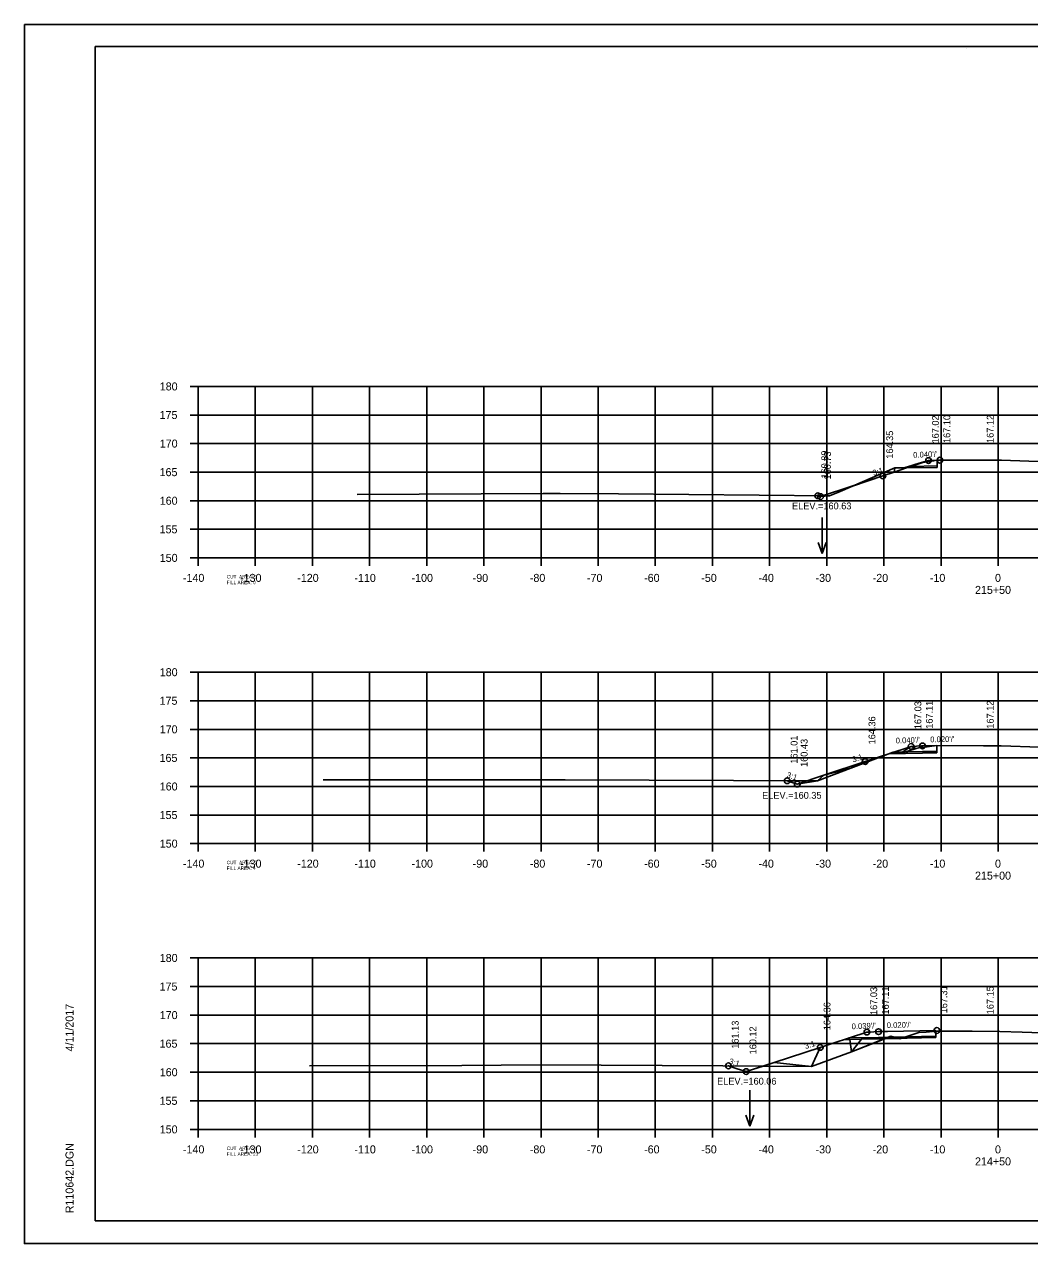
# Model space of a CAD drawing. Extents: x 1368503 to 1373085, y 379840 to 381833.
# Drawn here: x 1368502.7 to 1368678.6, y 381406.1 to 381619.4 of the extents above; entities that cross this region are included whole.
import ezdxf

# ---------------------------------------------------------------- set-up
doc = ezdxf.new("R2010")
doc.units = 0
for name, color, linetype in [('S_BRIDGE', 7, 'Continuous'), ('S_EDGE_PAVEMENT', 7, 'Continuous'), ('S_GRAVEL_ROAD', 7, 'Continuous'), ('S_MISC_BOUNDARY', 7, 'Continuous'), ('S_OBSCURES', 7, 'Continuous'), ('S_PHOTO_CENTERS', 7, 'Continuous'), ('S_PHOTO_NOTES', 7, 'Continuous'), ('S_RDW_PT_SYM', 7, 'Continuous'), ('S_SHOULDER', 7, 'Continuous'), ('S_STREAM_ANNOT', 7, 'Continuous'), ('S_TRAILS', 7, 'Continuous'), ('S_TRAILS_ANNOT', 7, 'Continuous'), ('S_TREE', 7, 'Continuous')]:
    doc.layers.add(name, color=color, linetype=linetype)

msp = doc.modelspace()

# ---------------------------------------------------------------- linework, layer by layer
at = {"layer": 'S_BRIDGE'}
for p, q in [((1368515.06, 381615.52), (1368831.24, 381615.52)), ((1368515.06, 381410.06), (1368515.06, 381615.52)), ((1368667.58, 381615.26), (1368667.58, 381615.26)), ((1368667.58, 381615.26), (1368667.58, 381615.26)), ((1368515.06, 381410.06), (1368515.06, 381410.06)), ((1368831.24, 381410.06), (1368515.06, 381410.06))]:
    msp.add_line(p, q, dxfattribs=at)
at = {"layer": 'S_EDGE_PAVEMENT'}
for p, q in [((1368531.66, 381556.06), (1368533.06, 381556.06)), ((1368533.06, 381526.06), (1368533.06, 381556.06)), ((1368531.66, 381551.06), (1368533.06, 381551.06)), ((1368531.66, 381546.06), (1368533.06, 381546.06)), ((1368531.66, 381541.06), (1368533.06, 381541.06)), ((1368531.66, 381536.06), (1368533.06, 381536.06)), ((1368531.66, 381531.06), (1368533.06, 381531.06)), ((1368531.66, 381526.06), (1368533.06, 381526.06)), ((1368533.06, 381526.06), (1368813.06, 381526.06)), ((1368533.06, 381524.66), (1368533.06, 381526.06)), ((1368543.06, 381524.66), (1368543.06, 381526.06)), ((1368553.06, 381524.66), (1368553.06, 381526.06)), ((1368563.06, 381524.66), (1368563.06, 381526.06)), ((1368573.06, 381524.66), (1368573.06, 381526.06)), ((1368583.06, 381524.66), (1368583.06, 381526.06)), ((1368593.06, 381524.66), (1368593.06, 381526.06)), ((1368603.06, 381524.66), (1368603.06, 381526.06)), ((1368613.06, 381524.66), (1368613.06, 381526.06)), ((1368623.06, 381524.66), (1368623.06, 381526.06)), ((1368633.06, 381524.66), (1368633.06, 381526.06)), ((1368643.06, 381524.66), (1368643.06, 381526.06)), ((1368653.06, 381524.66), (1368653.06, 381526.06)), ((1368663.06, 381524.66), (1368663.06, 381526.06)), ((1368673.06, 381524.66), (1368673.06, 381526.06)), ((1368531.66, 381506.06), (1368533.06, 381506.06)), ((1368533.06, 381476.06), (1368533.06, 381506.06)), ((1368531.66, 381501.06), (1368533.06, 381501.06)), ((1368531.66, 381496.06), (1368533.06, 381496.06)), ((1368531.66, 381491.06), (1368533.06, 381491.06)), ((1368531.66, 381486.06), (1368533.06, 381486.06)), ((1368531.66, 381481.06), (1368533.06, 381481.06)), ((1368531.66, 381476.06), (1368533.06, 381476.06)), ((1368533.06, 381476.06), (1368813.06, 381476.06)), ((1368533.06, 381474.66), (1368533.06, 381476.06)), ((1368543.06, 381474.66), (1368543.06, 381476.06)), ((1368553.06, 381474.66), (1368553.06, 381476.06)), ((1368563.06, 381474.66), (1368563.06, 381476.06)), ((1368573.06, 381474.66), (1368573.06, 381476.06)), ((1368583.06, 381474.66), (1368583.06, 381476.06)), ((1368593.06, 381474.66), (1368593.06, 381476.06)), ((1368603.06, 381474.66), (1368603.06, 381476.06)), ((1368613.06, 381474.66), (1368613.06, 381476.06)), ((1368623.06, 381474.66), (1368623.06, 381476.06)), ((1368633.06, 381474.66), (1368633.06, 381476.06)), ((1368643.06, 381474.66), (1368643.06, 381476.06)), ((1368653.06, 381474.66), (1368653.06, 381476.06)), ((1368663.06, 381474.66), (1368663.06, 381476.06)), ((1368673.06, 381474.66), (1368673.06, 381476.06)), ((1368531.66, 381456.06), (1368533.06, 381456.06)), ((1368533.06, 381426.06), (1368533.06, 381456.06)), ((1368531.66, 381451.06), (1368533.06, 381451.06)), ((1368531.66, 381446.06), (1368533.06, 381446.06)), ((1368531.66, 381441.06), (1368533.06, 381441.06)), ((1368531.66, 381436.06), (1368533.06, 381436.06)), ((1368531.66, 381431.06), (1368533.06, 381431.06)), ((1368531.66, 381426.06), (1368533.06, 381426.06)), ((1368533.06, 381426.06), (1368813.06, 381426.06)), ((1368533.06, 381424.66), (1368533.06, 381426.06)), ((1368543.06, 381424.66), (1368543.06, 381426.06)), ((1368553.06, 381424.66), (1368553.06, 381426.06)), ((1368563.06, 381424.66), (1368563.06, 381426.06)), ((1368573.06, 381424.66), (1368573.06, 381426.06)), ((1368583.06, 381424.66), (1368583.06, 381426.06)), ((1368593.06, 381424.66), (1368593.06, 381426.06)), ((1368603.06, 381424.66), (1368603.06, 381426.06)), ((1368613.06, 381424.66), (1368613.06, 381426.06)), ((1368623.06, 381424.66), (1368623.06, 381426.06)), ((1368633.06, 381424.66), (1368633.06, 381426.06)), ((1368643.06, 381424.66), (1368643.06, 381426.06)), ((1368653.06, 381424.66), (1368653.06, 381426.06)), ((1368663.06, 381424.66), (1368663.06, 381426.06)), ((1368673.06, 381424.66), (1368673.06, 381426.06))]:
    msp.add_line(p, q, dxfattribs=at)
at = {"layer": 'S_GRAVEL_ROAD'}
for p, q in [((1368642.24, 381533.11), (1368642.24, 381526.82)), ((1368642.24, 381526.82), (1368641.54, 381528.75)), ((1368642.24, 381526.82), (1368642.94, 381528.75)), ((1368629.61, 381432.9), (1368629.61, 381426.61)), ((1368629.61, 381426.61), (1368628.91, 381428.54)), ((1368629.61, 381426.61), (1368630.31, 381428.54))]:
    msp.add_line(p, q, dxfattribs=at)
at = {"layer": 'S_MISC_BOUNDARY'}
for points in [[(1368560.89, 381537.13), (1368593.43, 381537.32), (1368594.68, 381537.33), (1368595.6, 381537.34), (1368596.42, 381537.33), (1368606.61, 381537.24), (1368643.53, 381536.94), (1368645.38, 381537.7), (1368654.95, 381541.84), (1368656.19, 381541.81), (1368656.53, 381541.81), (1368657.16, 381542.01), (1368659.22, 381542.66), (1368661.73, 381543.04), (1368662.39, 381543.13), (1368672.21, 381543.17), (1368673.63, 381543.17), (1368681.6, 381542.84)], [(1368554.91, 381487.22), (1368579.94, 381487.25), (1368591.4, 381487.25), (1368597.27, 381487.23), (1368641.43, 381487.04), (1368647.27, 381489.25), (1368654.66, 381492.05), (1368655.24, 381491.98), (1368655.98, 381491.86), (1368658.7, 381492.68), (1368659.18, 381492.84), (1368659.74, 381492.9), (1368662.32, 381493.22), (1368670.48, 381493.19), (1368673.59, 381493.17), (1368680.27, 381492.92)], [(1368552.55, 381437.16), (1368579.2, 381437.26), (1368592.98, 381437.37), (1368624.85, 381437.21), (1368640.41, 381437.08), (1368647.36, 381439.64), (1368654.29, 381442.35), (1368654.66, 381442.27), (1368655.85, 381441.92), (1368657.8, 381442.54), (1368659.15, 381443.01), (1368660.43, 381443.1), (1368662.13, 381443.25), (1368668.51, 381443.22), (1368673.33, 381443.2), (1368677.23, 381443.09), (1368682.36, 381442.92)]]:
    msp.add_lwpolyline(points, dxfattribs=at)
at = {"layer": 'S_OBSCURES'}
for points in [[(1368662.39, 381541.9), (1368657.01, 381541.79)], [(1368662.39, 381542.15), (1368657.8, 381542.06)], [(1368662.32, 381491.96), (1368659.81, 381491.91), (1368653.93, 381491.79)], [(1368662.32, 381492.21), (1368659.81, 381492.16), (1368654.73, 381492.06)], [(1368662.13, 381442.11), (1368652.13, 381441.91), (1368646.14, 381441.79)], [(1368662.13, 381442.36), (1368652.13, 381442.16), (1368646.95, 381442.06)]]:
    msp.add_lwpolyline(points, dxfattribs=at)
at = {"layer": 'S_PHOTO_CENTERS'}
for p, q in [((1368533.06, 381556.06), (1368813.06, 381556.06)), ((1368533.06, 381526.06), (1368533.06, 381556.06)), ((1368543.06, 381526.06), (1368543.06, 381556.06)), ((1368553.06, 381526.06), (1368553.06, 381556.06)), ((1368563.06, 381526.06), (1368563.06, 381556.06)), ((1368573.06, 381526.06), (1368573.06, 381556.06)), ((1368583.06, 381526.06), (1368583.06, 381556.06)), ((1368593.06, 381526.06), (1368593.06, 381556.06)), ((1368603.06, 381526.06), (1368603.06, 381556.06)), ((1368613.06, 381526.06), (1368613.06, 381556.06)), ((1368623.06, 381526.06), (1368623.06, 381556.06)), ((1368633.06, 381526.06), (1368633.06, 381556.06)), ((1368643.06, 381526.06), (1368643.06, 381556.06)), ((1368653.06, 381526.06), (1368653.06, 381556.06)), ((1368663.06, 381526.06), (1368663.06, 381556.06)), ((1368673.06, 381526.06), (1368673.06, 381556.06)), ((1368533.06, 381551.06), (1368813.06, 381551.06)), ((1368533.06, 381546.06), (1368813.06, 381546.06)), ((1368533.06, 381541.06), (1368813.06, 381541.06)), ((1368533.06, 381536.06), (1368813.06, 381536.06)), ((1368533.06, 381531.06), (1368813.06, 381531.06)), ((1368533.06, 381526.06), (1368813.06, 381526.06)), ((1368533.06, 381506.06), (1368813.06, 381506.06)), ((1368533.06, 381476.06), (1368533.06, 381506.06)), ((1368543.06, 381476.06), (1368543.06, 381506.06)), ((1368553.06, 381476.06), (1368553.06, 381506.06)), ((1368563.06, 381476.06), (1368563.06, 381506.06)), ((1368573.06, 381476.06), (1368573.06, 381506.06)), ((1368583.06, 381476.06), (1368583.06, 381506.06)), ((1368593.06, 381476.06), (1368593.06, 381506.06)), ((1368603.06, 381476.06), (1368603.06, 381506.06)), ((1368613.06, 381476.06), (1368613.06, 381506.06)), ((1368623.06, 381476.06), (1368623.06, 381506.06)), ((1368633.06, 381476.06), (1368633.06, 381506.06)), ((1368643.06, 381476.06), (1368643.06, 381506.06)), ((1368653.06, 381476.06), (1368653.06, 381506.06)), ((1368663.06, 381476.06), (1368663.06, 381506.06)), ((1368673.06, 381476.06), (1368673.06, 381506.06)), ((1368533.06, 381501.06), (1368813.06, 381501.06)), ((1368533.06, 381496.06), (1368813.06, 381496.06)), ((1368533.06, 381491.06), (1368813.06, 381491.06)), ((1368533.06, 381486.06), (1368813.06, 381486.06)), ((1368533.06, 381481.06), (1368813.06, 381481.06)), ((1368533.06, 381476.06), (1368813.06, 381476.06)), ((1368533.06, 381456.06), (1368813.06, 381456.06)), ((1368533.06, 381426.06), (1368533.06, 381456.06)), ((1368543.06, 381426.06), (1368543.06, 381456.06)), ((1368553.06, 381426.06), (1368553.06, 381456.06)), ((1368563.06, 381426.06), (1368563.06, 381456.06)), ((1368573.06, 381426.06), (1368573.06, 381456.06)), ((1368583.06, 381426.06), (1368583.06, 381456.06)), ((1368593.06, 381426.06), (1368593.06, 381456.06)), ((1368603.06, 381426.06), (1368603.06, 381456.06)), ((1368613.06, 381426.06), (1368613.06, 381456.06)), ((1368623.06, 381426.06), (1368623.06, 381456.06)), ((1368633.06, 381426.06), (1368633.06, 381456.06)), ((1368643.06, 381426.06), (1368643.06, 381456.06)), ((1368653.06, 381426.06), (1368653.06, 381456.06)), ((1368663.06, 381426.06), (1368663.06, 381456.06)), ((1368673.06, 381426.06), (1368673.06, 381456.06)), ((1368533.06, 381451.06), (1368813.06, 381451.06)), ((1368533.06, 381446.06), (1368813.06, 381446.06)), ((1368533.06, 381441.06), (1368813.06, 381441.06)), ((1368533.06, 381436.06), (1368813.06, 381436.06)), ((1368533.06, 381431.06), (1368813.06, 381431.06)), ((1368533.06, 381426.06), (1368813.06, 381426.06))]:
    msp.add_line(p, q, dxfattribs=at)
at = {"layer": 'S_PHOTO_NOTES'}
for p, q in [((1368502.66, 381619.41), (1368835.99, 381619.41)), ((1368502.66, 381406.08), (1368835.99, 381406.08))]:
    msp.add_line(p, q, dxfattribs=at)
for points in [[(1368502.65, 381619.41), (1368835.99, 381619.41), (1368835.99, 381406.07), (1368502.65, 381406.07)], [(1368748.98, 381615.52), (1368748.98, 381605.64), (1368784.71, 381605.64), (1368784.71, 381602.72), (1368807.91, 381602.72), (1368807.91, 381578.38), (1368831.24, 381578.38), (1368831.24, 381410.06), (1368515.06, 381410.06), (1368515.06, 381615.52)], [(1368647.54, 381538.63), (1368654.95, 381541.84), (1368654.88, 381541.08), (1368652.87, 381540.41)], [(1368656.53, 381541.81), (1368657.16, 381542.01), (1368657.01, 381541.79)], [(1368657.16, 381542.01), (1368659.22, 381542.66), (1368658.99, 381542.45)], [(1368659.22, 381542.66), (1368661.73, 381543.04), (1368660.87, 381543.08)], [(1368661.73, 381543.04), (1368662.39, 381543.13), (1368662.39, 381543.14), (1368661.83, 381543.12)], [(1368645.38, 381537.7), (1368647.54, 381538.63), (1368647.42, 381538.6)], [(1368641.5, 381536.94), (1368641.5, 381536.96), (1368643.53, 381536.94), (1368641.98, 381536.78), (1368641.89, 381536.82)], [(1368655.98, 381491.86), (1368658.7, 381492.68), (1368657.81, 381493.08), (1368657.63, 381493.02)], [(1368659.18, 381492.84), (1368659.74, 381492.9), (1368659.7, 381493.16)], [(1368659.74, 381492.9), (1368662.32, 381493.22), (1368659.81, 381493.16)], [(1368662.32, 381493.22), (1368670.48, 381493.19), (1368662.32, 381493.21)], [(1368647.27, 381489.25), (1368654.66, 381492.05), (1368653.93, 381491.79), (1368649.78, 381490.42), (1368649.77, 381490.42)], [(1368641.43, 381487.04), (1368647.27, 381489.25), (1368642.53, 381488.02)], [(1368636.14, 381487.06), (1368641.43, 381487.04), (1368637.9, 381486.48), (1368637.35, 381486.66)], [(1368640.41, 381437.08), (1368647.36, 381439.64), (1368647.08, 381441.81), (1368646.14, 381441.79), (1368645.06, 381441.44), (1368641.91, 381440.41)], [(1368647.36, 381439.64), (1368653.23, 381441.93), (1368652.13, 381441.91), (1368649.11, 381441.85)], [(1368653.23, 381441.93), (1368654.29, 381442.35), (1368654.66, 381442.27), (1368655.63, 381441.98)], [(1368660.43, 381443.1), (1368662.13, 381443.25), (1368662.13, 381443.36)], [(1368625.84, 381437.18), (1368625.84, 381437.2), (1368631.92, 381437.15), (1368628.94, 381436.18), (1368627.4, 381436.68)], [(1368631.92, 381437.15), (1368640.41, 381437.08), (1368633.88, 381437.79)]]:
    msp.add_lwpolyline(points, close=True, dxfattribs=at)
for centre in [(1368662.87, 381543.16), (1368660.87, 381543.08), (1368652.87, 381540.41), (1368641.5, 381536.94), (1368641.98, 381536.78), (1368657.81, 381493.08), (1368659.81, 381493.16), (1368649.77, 381490.42), (1368636.14, 381487.06), (1368637.9, 381486.48), (1368650.08, 381443.08), (1368652.13, 381443.16), (1368662.34, 381443.36), (1368641.91, 381440.41), (1368625.84, 381437.18), (1368628.94, 381436.18)]:
    msp.add_circle(centre, 0.5, dxfattribs=at)
at = {"layer": 'S_STREAM_ANNOT'}
for points in [[(1368641.5, 381536.94), (1368641.89, 381536.82), (1368641.98, 381536.78), (1368647.42, 381538.6), (1368652.87, 381540.41), (1368654.88, 381541.08), (1368657.01, 381541.79), (1368658.99, 381542.45), (1368660.87, 381543.08), (1368661.83, 381543.12), (1368662.39, 381543.14)], [(1368636.14, 381487.06), (1368637.35, 381486.66), (1368637.9, 381486.48), (1368642.53, 381488.02), (1368649.77, 381490.42), (1368649.78, 381490.42), (1368653.93, 381491.79), (1368657.63, 381493.02), (1368657.81, 381493.08), (1368659.7, 381493.16), (1368659.81, 381493.16), (1368662.32, 381493.21)], [(1368625.84, 381437.18), (1368627.4, 381436.68), (1368628.94, 381436.18), (1368633.88, 381437.79), (1368641.91, 381440.41), (1368645.06, 381441.44), (1368646.14, 381441.79), (1368647.04, 381442.09), (1368650.08, 381443.08), (1368650.47, 381443.1), (1368652.13, 381443.16), (1368653.7, 381443.19), (1368662.13, 381443.36)]]:
    msp.add_lwpolyline(points, dxfattribs=at)
at = {"layer": 'S_TREE'}
for p, q in [((1368662.39, 381541.9), (1368662.39, 381543.14)), ((1368662.32, 381491.96), (1368662.32, 381493.21)), ((1368662.13, 381442.11), (1368662.13, 381443.36))]:
    msp.add_line(p, q, dxfattribs=at)

# ---------------------------------------------------------------- texts
at = {"layer": 'S_BRIDGE'}
for s, p in [('4/11/2017', (1368511.25, 381439.7)), ('R110642.DGN', (1368511.25, 381411.38))]:
    msp.add_text(s, height=1.4, rotation=90, dxfattribs=at).set_placement(p)
at = {"layer": 'S_GRAVEL_ROAD'}
for s, p in [('ELEV.=160.63', (1368636.98, 381534.55)), ('ELEV.=160.35', (1368631.75, 381483.91)), ('ELEV.=160.06', (1368623.87, 381433.89))]:
    msp.add_text(s, height=1.2, dxfattribs=at).set_placement(p)
at = {"layer": 'S_RDW_PT_SYM'}
for s, rotation, p in [("0.040'/'", 2.2905, (1368658.2, 381543.57)), ('3:1', 18.4339, (1368651.27, 381540.4)), ("0.040'/'", 2.2807, (1368655.14, 381493.58)), ("0.020'/'", 1.1405, (1368661.17, 381493.79)), ('3:1', 18.3419, (1368647.69, 381490.26)), ('3:1', 341.7423, (1368635.95, 381487.68)), ("0.039'/'", 2.2588, (1368647.43, 381443.58)), ("0.020'/'", 1.1379, (1368653.57, 381443.79)), ('3:1', 18.0831, (1368639.36, 381440.1)), ('3:1', 342.0455, (1368625.87, 381437.59))]:
    msp.add_text(s, height=1, rotation=rotation, dxfattribs=at).set_placement(p)
at = {"layer": 'S_SHOULDER'}
for s, p in [('167.02', (1368662.67, 381546.08)), ('167.10', (1368664.67, 381546.16)), ('164.35', (1368654.67, 381543.41)), ('160.89', (1368643.3, 381539.94)), ('160.73', (1368643.78, 381539.78)), ('167.11', (1368661.61, 381496.16)), ('167.03', (1368659.61, 381496.08)), ('164.36', (1368651.57, 381493.42)), ('161.01', (1368637.94, 381490.06)), ('160.43', (1368639.7, 381489.48)), ('167.03', (1368651.88, 381446.08)), ('167.11', (1368653.93, 381446.16)), ('167.31', (1368664.14, 381446.36)), ('164.36', (1368643.71, 381443.41)), ('161.13', (1368627.64, 381440.18)), ('160.12', (1368630.74, 381439.18))]:
    msp.add_text(s, height=1.2, rotation=90, dxfattribs=at).set_placement(p)
at = {"layer": 'S_TRAILS'}
for s, height, p in [('180', 1.4, (1368526.34, 381555.36)), ('175', 1.4, (1368526.31, 381550.36)), ('170', 1.4, (1368526.34, 381545.36)), ('165', 1.4, (1368526.31, 381540.36)), ('160', 1.4, (1368526.34, 381535.36)), ('155', 1.4, (1368526.31, 381530.36)), ('150', 1.4, (1368526.34, 381525.36)), ('-140', 1.4, (1368530.4, 381521.86)), ('CUT  AREA: 3', 0.6, (1368538.06, 381522.46)), ('-130', 1.4, (1368540.4, 381521.86)), ('-120', 1.4, (1368550.4, 381521.86)), ('-110', 1.4, (1368560.4, 381521.86)), ('-100', 1.4, (1368570.4, 381521.86)), ('-90', 1.4, (1368581.1, 381521.86)), ('-80', 1.4, (1368591.1, 381521.86)), ('-70', 1.4, (1368601.1, 381521.86)), ('-60', 1.4, (1368611.1, 381521.86)), ('-50', 1.4, (1368621.1, 381521.86)), ('-40', 1.4, (1368631.1, 381521.86)), ('-30', 1.4, (1368641.1, 381521.86)), ('-20', 1.4, (1368651.1, 381521.86)), ('-10', 1.4, (1368661.1, 381521.86)), ('0', 1.4, (1368672.5, 381521.86)), ('FILL AREA: 0', 0.6, (1368538.06, 381521.46)), ('215+50', 1.4, (1368669, 381519.76)), ('180', 1.4, (1368526.34, 381505.36)), ('175', 1.4, (1368526.31, 381500.36)), ('170', 1.4, (1368526.34, 381495.36)), ('165', 1.4, (1368526.31, 381490.36)), ('160', 1.4, (1368526.34, 381485.36)), ('155', 1.4, (1368526.31, 381480.36)), ('150', 1.4, (1368526.34, 381475.36)), ('-140', 1.4, (1368530.4, 381471.86)), ('-130', 1.4, (1368540.4, 381471.86)), ('-120', 1.4, (1368550.4, 381471.86)), ('-110', 1.4, (1368560.4, 381471.86)), ('-100', 1.4, (1368570.4, 381471.86)), ('-90', 1.4, (1368581.1, 381471.86)), ('-80', 1.4, (1368591.1, 381471.86)), ('-70', 1.4, (1368601.1, 381471.86)), ('-60', 1.4, (1368611.1, 381471.86)), ('-50', 1.4, (1368621.1, 381471.86)), ('-40', 1.4, (1368631.1, 381471.86)), ('-30', 1.4, (1368641.1, 381471.86)), ('-20', 1.4, (1368651.1, 381471.86)), ('-10', 1.4, (1368661.1, 381471.86)), ('0', 1.4, (1368672.5, 381471.86)), ('CUT  AREA: 2', 0.6, (1368538.06, 381472.46)), ('FILL AREA: 4', 0.6, (1368538.06, 381471.46)), ('215+00', 1.4, (1368669, 381469.76)), ('180', 1.4, (1368526.34, 381455.36)), ('175', 1.4, (1368526.31, 381450.36)), ('170', 1.4, (1368526.34, 381445.36)), ('165', 1.4, (1368526.31, 381440.36)), ('160', 1.4, (1368526.34, 381435.36)), ('155', 1.4, (1368526.31, 381430.36)), ('150', 1.4, (1368526.34, 381425.36)), ('-140', 1.4, (1368530.4, 381421.86)), ('CUT  AREA: 4', 0.6, (1368538.06, 381422.46)), ('FILL AREA: 23', 0.6, (1368538.06, 381421.46)), ('-130', 1.4, (1368540.4, 381421.86)), ('-120', 1.4, (1368550.4, 381421.86)), ('-110', 1.4, (1368560.4, 381421.86)), ('-100', 1.4, (1368570.4, 381421.86)), ('-90', 1.4, (1368581.1, 381421.86)), ('-80', 1.4, (1368591.1, 381421.86)), ('-70', 1.4, (1368601.1, 381421.86)), ('-60', 1.4, (1368611.1, 381421.86)), ('-50', 1.4, (1368621.1, 381421.86)), ('-40', 1.4, (1368631.1, 381421.86)), ('-30', 1.4, (1368641.1, 381421.86)), ('-20', 1.4, (1368651.1, 381421.86)), ('-10', 1.4, (1368661.1, 381421.86)), ('0', 1.4, (1368672.5, 381421.86)), ('214+50', 1.4, (1368669, 381419.76))]:
    msp.add_text(s, height=height, dxfattribs=at).set_placement(p)
at = {"layer": 'S_TRAILS_ANNOT'}
for s, p in [('167.12', (1368672.26, 381546.17)), ('167.12', (1368672.26, 381496.18)), ('167.15', (1368672.26, 381446.2))]:
    msp.add_text(s, height=1.2, rotation=90, dxfattribs=at).set_placement(p)

doc.saveas('drawing.dxf')
